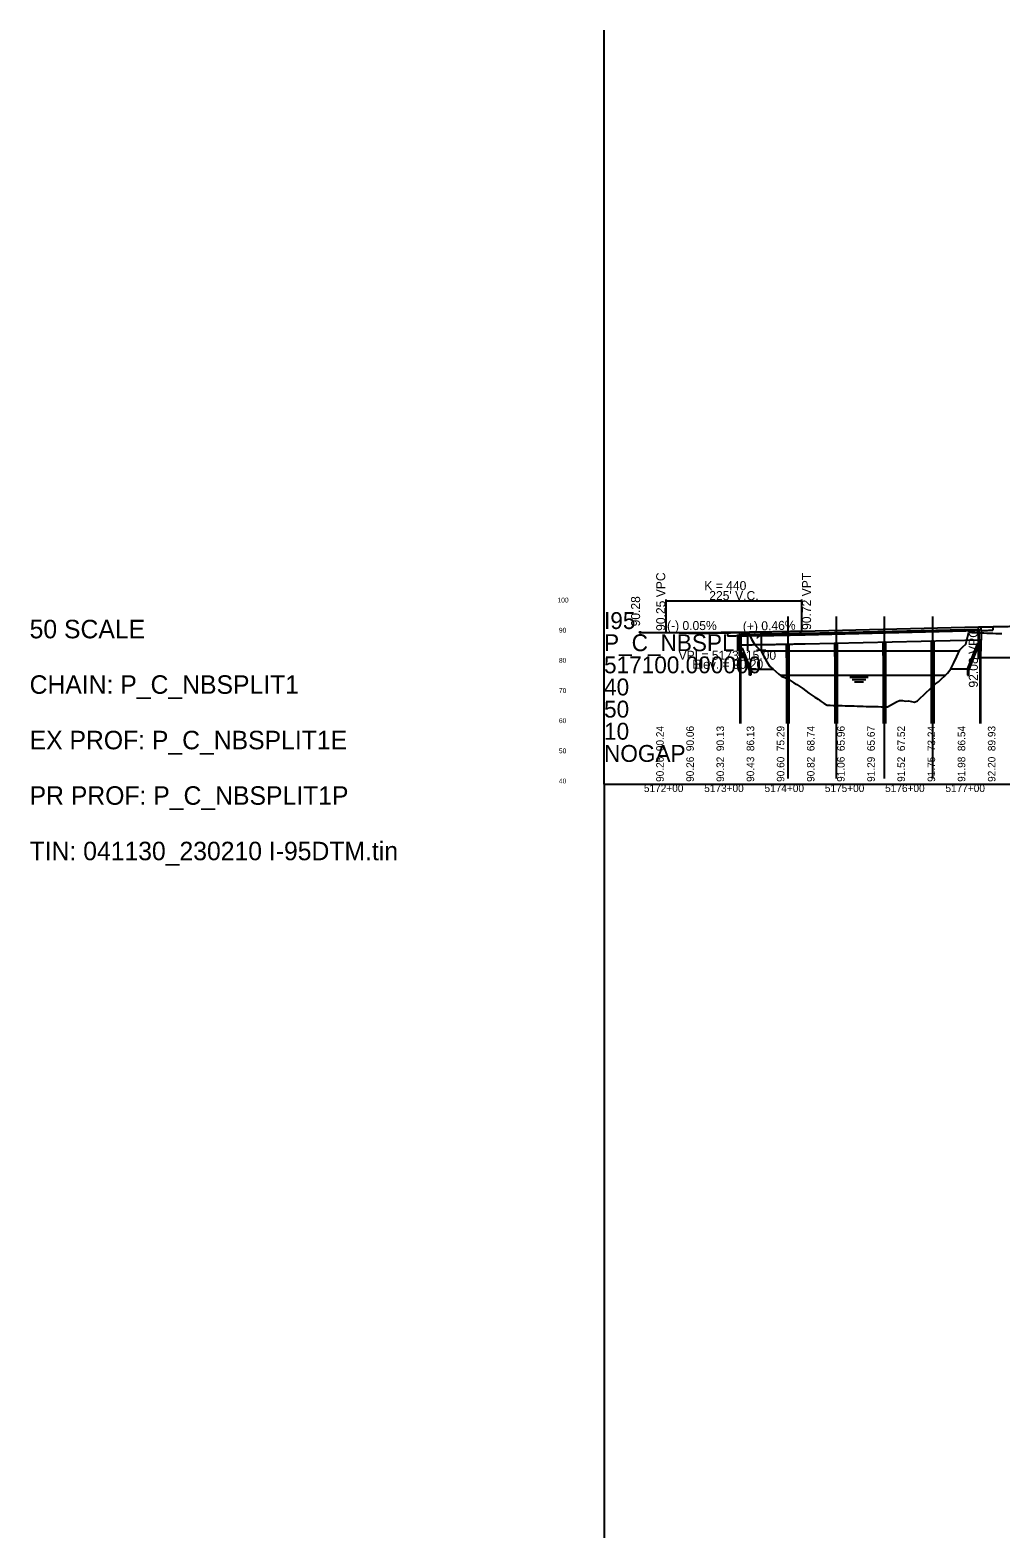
# Model space of a CAD drawing. Extents: x 2121671 to 2169879, y 557274 to 599957.
# Drawn here: x 2145716 to 2147326, y 580937 to 583437 of the extents above; entities that cross this region are included whole.
import ezdxf

# ---------------------------------------------------------------- set-up
doc = ezdxf.new("R2010")
doc.units = 0
for name, color, linetype in [('BR_CENTER LINES', 7, 'Continuous'), ('BR_CONCRETE', 7, 'Continuous'), ('BR_DETAILS', 7, 'Continuous'), ('BR_PRESTRESSED BEAM', 7, 'Continuous'), ('BR_STRUCTURAL STEEL', 7, 'Continuous'), ('RD_DDB_ElevTX', 7, 'Continuous'), ('RD_DDB_GradeTX', 7, 'Continuous'), ('RD_DDB_Profile_Elev', 7, 'Continuous'), ('RD_DDB_Profile_EX', 7, 'Continuous'), ('RD_DDB_Profile_Lbl', 7, 'Continuous'), ('RD_DDB_Profile_PR', 7, 'Continuous'), ('RD_DDB_StaTX', 7, 'Continuous'), ('RD_DDB_StripGrade', 7, 'Continuous'), ('RD_DDB_VCLbl', 7, 'Continuous'), ('RD_GPK_Profile_Cell', 7, 'Continuous'), ('RD_HC_Data_Rel', 7, 'Continuous')]:
    doc.layers.add(name, color=color, linetype=linetype)

msp = doc.modelspace()

# ---------------------------------------------------------------- linework, layer by layer
at = {"layer": 'BR_CENTER LINES'}
for p, q in [((2146972.6, 582464.6), (2146972.6, 582195.8)), ((2147052.6, 582464.6), (2147052.6, 582316.5)), ((2147052.6, 582464.6), (2147052.6, 582195.8)), ((2147132.6, 582464.6), (2147132.6, 582314.4)), ((2147132.6, 582464.6), (2147132.6, 582195.8)), ((2147212.6, 582464.6), (2147212.6, 582339.1)), ((2147212.6, 582464.6), (2147212.6, 582195.8))]:
    msp.add_line(p, q, dxfattribs=at)
at = {"layer": 'BR_CONCRETE'}
for p, q in [((2146872.6, 582438.5), (2146872.6, 582432.6)), ((2146892, 582432.8), (2146892, 582416.9)), ((2146892.6, 582438.7), (2146892.6, 582432.8)), ((2146895.5, 582416.9), (2146895.5, 582435.2)), ((2147001.4, 582436.9), (2147289.8, 582443.6)), ((2147289.8, 582425.4), (2147289.8, 582443.6)), ((2147292.6, 582447.2), (2147292.6, 582441.4)), ((2147292.6, 582441.4), (2147294.8, 582441.4)), ((2147293.3, 582441.3), (2147293.3, 582425.4)), ((2147312.6, 582447.6), (2147312.6, 582441.8)), ((2147210.6, 582401.8), (2147210.6, 582287.1)), ((2147214.6, 582401.8), (2147214.6, 582287.1)), ((2146970.6, 582396.3), (2146970.6, 582287.1)), ((2146974.6, 582396.3), (2146974.6, 582287.1)), ((2147050.6, 582398.1), (2147050.6, 582287.1)), ((2147054.6, 582398.1), (2147054.6, 582287.1)), ((2147130.6, 582399.9), (2147130.6, 582287.1)), ((2147134.6, 582399.9), (2147134.6, 582287.1))]:
    msp.add_line(p, q, dxfattribs=at)
for points in [[(2147289.8, 582407.9), (2147293.3, 582407.9), (2147293.3, 582425.4), (2147289.8, 582425.4)], [(2146892, 582399.4), (2146895.5, 582399.4), (2146895.5, 582416.9), (2146892, 582416.9)], [(2146970.1, 582396.3), (2146975.1, 582396.3), (2146975.1, 582416.3), (2146970.1, 582416.3)], [(2147050.1, 582398.1), (2147055.1, 582398.1), (2147055.1, 582418.1), (2147050.1, 582418.1)], [(2147130.1, 582399.9), (2147135.1, 582399.9), (2147135.1, 582419.9), (2147130.1, 582419.9)], [(2147210.1, 582401.8), (2147215.1, 582401.8), (2147215.1, 582421.8), (2147210.1, 582421.8)]]:
    msp.add_lwpolyline(points, close=True, dxfattribs=at)
for points in [[(2146872.6, 582432.6), (2146875.4, 582432.7), (2146879.9, 582432.7), (2146884.4, 582432.7), (2146888.9, 582432.8), (2146892.6, 582432.8)], [(2146895.5, 582435.1), (2146897.9, 582435.2), (2146902.4, 582435.2), (2146906.9, 582435.3), (2146911.4, 582435.3), (2146915.9, 582435.4), (2146920.4, 582435.4), (2146924.9, 582435.5), (2146929.4, 582435.6), (2146933.9, 582435.6), (2146938.4, 582435.7), (2146942.9, 582435.8), (2146947.4, 582435.8), (2146951.9, 582435.9), (2146956.4, 582436), (2146960.9, 582436.1), (2146965.4, 582436.2), (2146969.9, 582436.2), (2146974.4, 582436.3), (2146978.9, 582436.4), (2146983.4, 582436.5), (2146987.9, 582436.6), (2146992.4, 582436.7), (2146996.9, 582436.8), (2147001.4, 582436.9)], [(2147294.8, 582441.4), (2147303.8, 582441.6), (2147312.6, 582441.8)]]:
    msp.add_spline(points, degree=3, dxfattribs=at)
at = {"layer": 'BR_DETAILS'}
for p, q in [((2146895.5, 582411.9), (2146897.5, 582411.9)), ((2146895.5, 582404.4), (2146897.5, 582404.4)), ((2146911.2, 582377.5), (2146897.5, 582411.9)), ((2146909.2, 582375), (2146897.5, 582404.4)), ((2147270.6, 582377.5), (2147287.8, 582420.4)), ((2147272.6, 582375), (2147287.8, 582412.9)), ((2147289.8, 582420.4), (2147287.8, 582420.4)), ((2147289.8, 582412.9), (2147287.8, 582412.9)), ((2146911.2, 582377.5), (2146911.2, 582367.5)), ((2146911.2, 582377.5), (2146947.9, 582377.5)), ((2147270.6, 582377.5), (2147242.5, 582377.5)), ((2147270.6, 582377.5), (2147270.6, 582367.5)), ((2146909.2, 582367.5), (2146909.2, 582375)), ((2146911.2, 582367.5), (2146909.2, 582367.5)), ((2147270.6, 582367.5), (2147272.6, 582367.5)), ((2147272.6, 582367.5), (2147272.6, 582375))]:
    msp.add_line(p, q, dxfattribs=at)
for points in [[(2146971.1, 582418.8), (2146972.1, 582418.8), (2146972.1, 582416.3), (2146971.1, 582416.3)], [(2146973.1, 582418.8), (2146974.1, 582418.8), (2146974.1, 582416.3), (2146973.1, 582416.3)], [(2147051.1, 582420.6), (2147052.1, 582420.6), (2147052.1, 582418.1), (2147051.1, 582418.1)], [(2147053.1, 582420.6), (2147054.1, 582420.6), (2147054.1, 582418.1), (2147053.1, 582418.1)], [(2147131.1, 582422.4), (2147132.1, 582422.4), (2147132.1, 582419.9), (2147131.1, 582419.9)], [(2147133.1, 582422.4), (2147134.1, 582422.4), (2147134.1, 582419.9), (2147133.1, 582419.9)], [(2147211.1, 582424.3), (2147212.1, 582424.3), (2147212.1, 582421.8), (2147211.1, 582421.8)], [(2147213.1, 582424.3), (2147214.1, 582424.3), (2147214.1, 582421.8), (2147213.1, 582421.8)]]:
    msp.add_lwpolyline(points, close=True, dxfattribs=at)
at = {"layer": 'BR_PRESTRESSED BEAM'}
for p, q in [((2147001.4, 582434.4), (2147289.8, 582441.1)), ((2147001.4, 582419.4), (2147289.8, 582426.1))]:
    msp.add_line(p, q, dxfattribs=at)
for points in [[(2146895.5, 582432.6), (2146897.9, 582432.7), (2146902.4, 582432.7), (2146906.9, 582432.8), (2146911.4, 582432.8), (2146915.9, 582432.9), (2146920.4, 582432.9), (2146924.9, 582433), (2146929.4, 582433.1), (2146933.9, 582433.1), (2146938.4, 582433.2), (2146942.9, 582433.3), (2146947.4, 582433.3), (2146951.9, 582433.4), (2146956.4, 582433.5), (2146960.9, 582433.6), (2146965.4, 582433.7), (2146969.9, 582433.7), (2146974.4, 582433.8), (2146978.9, 582433.9), (2146983.4, 582434), (2146987.9, 582434.1), (2146992.4, 582434.2), (2146996.9, 582434.3), (2147001.4, 582434.4)], [(2146895.5, 582417.6), (2146897.9, 582417.7), (2146902.4, 582417.7), (2146906.9, 582417.8), (2146911.4, 582417.8), (2146915.9, 582417.9), (2146920.4, 582417.9), (2146924.9, 582418), (2146929.4, 582418.1), (2146933.9, 582418.1), (2146938.4, 582418.2), (2146942.9, 582418.3), (2146947.4, 582418.3), (2146951.9, 582418.4), (2146956.4, 582418.5), (2146960.9, 582418.6), (2146965.4, 582418.7), (2146969.9, 582418.7), (2146974.4, 582418.8), (2146978.9, 582418.9), (2146983.4, 582419), (2146987.9, 582419.1), (2146992.4, 582419.2), (2146996.9, 582419.3), (2147001.4, 582419.4)]]:
    msp.add_spline(points, degree=3, dxfattribs=at)
at = {"layer": 'BR_STRUCTURAL STEEL'}
for p, q in [((2147291, 582407.9), (2147291, 582287.1)), ((2147292.1, 582407.9), (2147292.1, 582287.1)), ((2146893.1, 582399.4), (2146893.1, 582287.1)), ((2146894.3, 582399.4), (2146894.3, 582287.1))]:
    msp.add_line(p, q, dxfattribs=at)
at = {"layer": 'RD_DDB_GradeTX'}
msp.add_line((2146820.9, 582438), (2146881.9, 582437.8), dxfattribs=at)
msp.add_circle((2146727.7, 582438.2), 1, dxfattribs=at)
at = {"layer": 'RD_DDB_Profile_Elev'}
for p, q in [((2146928.1, 582407.4), (2147256.9, 582407.4)), ((2146960, 582367.4), (2147234.4, 582367.4)), ((2147075.7, 582363.7), (2147105.7, 582363.7)), ((2147079.5, 582359.9), (2147102, 582359.9)), ((2147083.2, 582356.2), (2147098.2, 582356.2))]:
    msp.add_line(p, q, dxfattribs=at)
at = {"layer": 'RD_DDB_Profile_EX'}
for points in [[(2146727.7, 582438.2), (2146732.7, 582438.1), (2146737.7, 582438), (2146742.7, 582437.9), (2146747.7, 582438), (2146752.7, 582438), (2146757.7, 582438), (2146762.7, 582438), (2146767.7, 582438), (2146772.7, 582438), (2146777.7, 582438.1), (2146782.7, 582438), (2146787.7, 582437.9), (2146792.7, 582437.7), (2146797.7, 582437.6), (2146802.7, 582437.4), (2146807.7, 582437.2), (2146812.7, 582437.2), (2146817.7, 582437.2), (2146822.7, 582437.1), (2146827.7, 582437.1), (2146832.7, 582437.1), (2146837.7, 582437.2), (2146842.7, 582437.2), (2146847.7, 582437.3), (2146852.7, 582437.3), (2146857.7, 582437.3), (2146862.7, 582437.4), (2146867.7, 582437.5), (2146872.7, 582437.6), (2146877.7, 582437.7), (2146882.7, 582437.8), (2146887.7, 582437.9), (2146892.7, 582437.9), (2146897.7, 582438), (2146902.7, 582438.1), (2146907.7, 582438.2), (2146912.7, 582426.9), (2146917.7, 582417.7), (2146922.7, 582412.6), (2146927.7, 582408.2), (2146932.7, 582398.8), (2146937.7, 582389.6), (2146942.7, 582381.7), (2146947.7, 582377.6), (2146952.7, 582373.5), (2146957.7, 582369.2), (2146962.7, 582365.3), (2146967.7, 582363.4), (2146972.7, 582361.2), (2146977.7, 582358), (2146982.7, 582354.8), (2146987.7, 582352), (2146992.7, 582348.6), (2146997.7, 582345.1), (2147002.7, 582341.2), (2147007.7, 582337.6), (2147012.7, 582334.1), (2147017.7, 582330.7), (2147022.7, 582327.3), (2147027.7, 582323.9), (2147032.7, 582320.5), (2147037.7, 582317.5), (2147042.7, 582317.3), (2147047.7, 582317.2), (2147052.7, 582317.1), (2147057.7, 582316.9), (2147062.7, 582316.8), (2147067.7, 582316.6), (2147072.7, 582316.5), (2147077.7, 582316.3), (2147082.7, 582316.2), (2147087.7, 582316.1), (2147092.7, 582315.9), (2147097.7, 582315.8), (2147102.7, 582315.6), (2147107.7, 582315.5), (2147112.7, 582315.4), (2147117.7, 582315.2), (2147122.7, 582315.1), (2147127.7, 582314.9), (2147132.7, 582314.8), (2147137.7, 582315), (2147142.7, 582317.6), (2147147.7, 582320.2), (2147152.7, 582322.8), (2147157.7, 582325.4), (2147162.7, 582325.5), (2147167.7, 582324.4), (2147172.7, 582324.6), (2147177.7, 582323.8), (2147182.7, 582322.7), (2147187.7, 582325), (2147192.7, 582329.6), (2147197.7, 582334.3), (2147202.7, 582338.9), (2147207.7, 582343.6), (2147212.7, 582348.3), (2147217.7, 582352.9), (2147222.7, 582356), (2147227.7, 582361.1)], [(2147227.7, 582361.1), (2147232.7, 582365.7), (2147237.7, 582370.7), (2147242.7, 582377.8), (2147247.7, 582387.8), (2147252.7, 582398.4), (2147257.7, 582409.3), (2147262.7, 582414.2), (2147267.7, 582418.8), (2147272.7, 582438.4), (2147277.7, 582438.2), (2147282.7, 582437.9), (2147287.7, 582437.7), (2147292.7, 582437.5), (2147297.7, 582437.3), (2147302.7, 582437.1), (2147307.7, 582436.9), (2147312.7, 582436.7), (2147317.7, 582436.5), (2147322.7, 582436.3), (2147327.7, 582436.3)]]:
    msp.add_lwpolyline(points, dxfattribs=at)
at = {"layer": 'RD_DDB_Profile_PR'}
for p, q in [((2146727.7, 582438.2), (2146770.4, 582438.1)), ((2146995.4, 582440.4), (2147288.8, 582447.2))]:
    msp.add_line(p, q, dxfattribs=at)
for points in [[(2146770.4, 582438.1), (2146774.9, 582438.1), (2146779.4, 582438.1), (2146783.9, 582438.1), (2146788.4, 582438.1), (2146792.9, 582438.1), (2146797.4, 582438.1), (2146801.9, 582438.1), (2146806.4, 582438.1), (2146810.9, 582438.1), (2146815.4, 582438.1), (2146819.9, 582438.1), (2146824.4, 582438.1), (2146828.9, 582438.2), (2146833.4, 582438.2), (2146837.9, 582438.2), (2146842.4, 582438.2), (2146846.9, 582438.2), (2146851.4, 582438.3), (2146855.9, 582438.3), (2146860.4, 582438.3), (2146864.9, 582438.4), (2146869.4, 582438.4), (2146873.9, 582438.5), (2146878.4, 582438.5), (2146882.9, 582438.5), (2146887.4, 582438.6), (2146891.9, 582438.6), (2146896.4, 582438.7), (2146900.9, 582438.8), (2146905.4, 582438.8), (2146909.9, 582438.9), (2146914.4, 582438.9), (2146918.9, 582439), (2146923.4, 582439.1), (2146927.9, 582439.1), (2146932.4, 582439.2), (2146936.9, 582439.3), (2146941.4, 582439.3), (2146945.9, 582439.4), (2146950.4, 582439.5), (2146954.9, 582439.6), (2146959.4, 582439.7), (2146963.9, 582439.8), (2146968.4, 582439.8), (2146972.9, 582439.9), (2146977.4, 582440), (2146981.9, 582440.1), (2146986.4, 582440.2), (2146990.9, 582440.3), (2146995.4, 582440.4)], [(2147288.8, 582447.2), (2147297.8, 582447.4), (2147306.8, 582447.6), (2147315.8, 582447.8), (2147324.8, 582448), (2147333.8, 582448.2), (2147342.8, 582448.3), (2147351.8, 582448.5), (2147360.8, 582448.6), (2147369.8, 582448.7), (2147378.8, 582448.9), (2147387.8, 582449), (2147396.8, 582449.1), (2147405.8, 582449.2), (2147414.8, 582449.3), (2147423.8, 582449.3), (2147432.8, 582449.4), (2147441.8, 582449.5), (2147450.8, 582449.5), (2147459.8, 582449.6), (2147468.8, 582449.6), (2147477.8, 582449.6), (2147486.8, 582449.6), (2147495.8, 582449.6), (2147504.8, 582449.6), (2147513.8, 582449.6), (2147522.8, 582449.6), (2147531.8, 582449.6), (2147540.8, 582449.5), (2147549.8, 582449.5), (2147558.8, 582449.4), (2147567.8, 582449.4), (2147576.8, 582449.3), (2147585.8, 582449.2), (2147594.8, 582449.1), (2147603.8, 582449), (2147612.8, 582448.9), (2147621.8, 582448.8), (2147630.8, 582448.6), (2147639.8, 582448.5), (2147648.8, 582448.4), (2147657.8, 582448.2), (2147666.8, 582448), (2147675.8, 582447.9), (2147684.8, 582447.7), (2147693.8, 582447.5), (2147702.8, 582447.3), (2147711.8, 582447.1), (2147720.8, 582446.9), (2147729.8, 582446.6), (2147738.8, 582446.4)]]:
    msp.add_spline(points, degree=3, dxfattribs=at)
at = {"layer": 'RD_DDB_VCLbl'}
for p, q in [((2146770.4, 582492.9), (2146770.4, 582438.1)), ((2146770.4, 582490.4), (2146995.4, 582490.4)), ((2146995.4, 582492.9), (2146995.4, 582440.4)), ((2147288.8, 582393.9), (2147288.8, 582447.2)), ((2147288.8, 582396.4), (2147738.8, 582396.4))]:
    msp.add_line(p, q, dxfattribs=at)
at = {"layer": 'RD_GPK_Profile_Cell'}
for q in [(2146667.9, 583436.8), (2151167.9, 582186.8), (2146667.9, 580936.8)]:
    msp.add_line((2146667.9, 582186.8), q, dxfattribs=at)

# ---------------------------------------------------------------- texts
at = {"layer": 'RD_DDB_ElevTX'}
for s, p in [('100', (2146590.7, 582487.8)), ('90', (2146593.1, 582437.8)), ('80', (2146593.1, 582387.8)), ('70', (2146593.1, 582337.8)), ('60', (2146593.1, 582287.8)), ('50', (2146593.1, 582237.8)), ('40', (2146593.1, 582187.8))]:
    msp.add_text(s, height=8, dxfattribs=at).set_placement(p)
at = {"layer": 'RD_DDB_GradeTX'}
for s, rotation, p in [('(-) 0.05%', 359.8609, (2146772.3, 582442.2)), ('(+) 0.46%', 1.3258, (2146898.2, 582440.8))]:
    msp.add_text(s, height=15, rotation=rotation, dxfattribs=at).set_placement(p)
at = {"layer": 'RD_DDB_Profile_Lbl'}
msp.add_text('90.28', height=15, rotation=90, dxfattribs=at).set_placement((2146727.7, 582448.1))
for s, p in [('VPI = 5173+15.00', (2146791.5, 582392.8)), ('Elev. = 90.20', (2146814.2, 582377.8))]:
    msp.add_text(s, height=15, dxfattribs=at).set_placement(p)
at = {"layer": 'RD_DDB_StaTX'}
for s, p in [('5172+00', (2146734, 582173.5)), ('5173+00', (2146834, 582173.5)), ('5174+00', (2146934, 582173.5)), ('5175+00', (2147034, 582173.5)), ('5176+00', (2147134, 582173.5)), ('5177+00', (2147234, 582173.5))]:
    msp.add_text(s, height=12.5, dxfattribs=at).set_placement(p)
at = {"layer": 'RD_DDB_StripGrade'}
for s, height, p in [('90.25 VPC', 15, (2146769.4, 582440.7)), ('90.72 VPT', 15, (2147011.2, 582442.3)), ('92.08 VPC', 15, (2147287.8, 582346.7)), ('90.24', 12.5, (2146766.9, 582241.3)), ('90.06', 12.5, (2146816.9, 582241.3)), ('90.13', 12.5, (2146866.9, 582241.3)), ('86.13', 12.5, (2146916.9, 582241.3)), ('75.29', 12.5, (2146966.9, 582241.3)), ('68.74', 12.5, (2147016.9, 582241.3)), ('65.96', 12.5, (2147066.9, 582241.3)), ('65.67', 12.5, (2147116.9, 582241.3)), ('67.52', 12.5, (2147166.9, 582241.3)), ('73.24', 12.5, (2147216.9, 582241.3)), ('86.54', 12.5, (2147266.9, 582241.3)), ('89.93', 12.5, (2147316.9, 582241.3)), ('90.26', 12.5, (2146766.9, 582190.3)), ('90.26', 12.5, (2146816.9, 582190.3)), ('90.32', 12.5, (2146866.9, 582190.3)), ('90.43', 12.5, (2146916.9, 582190.3)), ('90.60', 12.5, (2146966.9, 582190.3)), ('90.82', 12.5, (2147016.9, 582190.3)), ('91.06', 12.5, (2147066.9, 582190.3)), ('91.29', 12.5, (2147116.9, 582190.3)), ('91.52', 12.5, (2147166.9, 582190.3)), ('91.75', 12.5, (2147216.9, 582190.3)), ('91.98', 12.5, (2147266.9, 582190.3)), ('92.20', 12.5, (2147316.9, 582190.3))]:
    msp.add_text(s, height=height, rotation=90, dxfattribs=at).set_placement(p)
at = {"layer": 'RD_DDB_VCLbl'}
for s, p in [('K = 440', (2146834.2, 582508.2)), ("225' V.C.", (2146842.4, 582491.7))]:
    msp.add_text(s, height=15, dxfattribs=at).set_placement(p)
at = {"layer": 'RD_GPK_Profile_Cell'}
for s, p in [('I95', (2146667.9, 582443.8)), ('P_C_NBSPLIT1', (2146667.9, 582407.1)), ('517100.000000', (2146667.9, 582370.4)), ('40', (2146667.9, 582333.7)), ('50', (2146667.9, 582297)), ('10', (2146667.9, 582260.3)), ('NOGAP', (2146667.9, 582223.5))]:
    msp.add_text(s, height=28, dxfattribs=at).set_placement(p)
at = {"layer": 'RD_HC_Data_Rel'}
for s, height, p in [('50 SCALE', 30.67, (2145715.4, 582428.4)), ('CHAIN: P_C_NBSPLIT1', 30.668, (2145715.4, 582336.4)), ('EX PROF: P_C_NBSPLIT1E', 30.668, (2145715.4, 582244.4)), ('PR PROF: P_C_NBSPLIT1P', 30.668, (2145715.4, 582152.4)), ('TIN: 041130_230210 I-95DTM.tin', 30.668, (2145715.4, 582060.4))]:
    msp.add_text(s, height=height, rotation=360, dxfattribs=at).set_placement(p)

doc.saveas('drawing.dxf')
